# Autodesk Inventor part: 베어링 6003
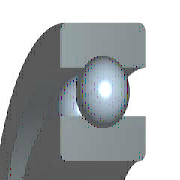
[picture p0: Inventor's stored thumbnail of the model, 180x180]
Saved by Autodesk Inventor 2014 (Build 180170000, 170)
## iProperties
Created: 2012-02
Part Number: 베어링 6003
Material: 강철, 연강
Description: 깊은 그루브 볼 베어링
Document SubType Name: Modeling
Standard: KS B 2023
Designer: mduedu
Standards Organization: KS
Language: ko-KR
Size Designation: 6003 - 17 x 35 x 10
Categories: <MemberInstance><Categories><Category DisplayName="샤프트 부품" InternalName="7f7aeb1f-a693-4053-b835-cee3144e0d98" Mnemonic="SHFT"><Category DisplayName="베어링" Inter
Density: 7.86 g/cm^3
Appearance: 주황색
Mass: 35.231 g
Surface Area: 48.7538 cm^2
Volume: 4.48231 cm^3
IsCustomPart: 1
Author: mduedu
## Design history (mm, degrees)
sketch "스케치" dims "d0" = 4.68 (= -0.26 x WD + 0.26 x BD)
  geometry: L1 (2.66, 13)-(7.34, 13); L2 (5, 13)-(5, 10.66); L3 (5, 13)-(5, 15.34); L4 (3.261, 11.434)-(0, 11.434); L5 (0, 8.5)-(10, 8.5); L6 (3.261, 14.566)-(0, 14.566); L7 (0, 17.5)-(10, 17.5); L8 (10, 8.5)-(10, 11.434); L9 (6.739, 11.434)-(10, 11.434); L10 (6.739, 14.566)-(10, 14.566); L11 (10, 17.5)-(10, 14.566); L12 (-1.4, 0)-(8.4, 0) reference; L13 (0, -0.3)-(0, 5.3) reference
  constraints: 22 end point, 4 point on line, 2 collinear, 2 perpendicular, 2 symmetric about line, 1 midpoint, 1 parallel, 14 other
  dimensions: "d9" = 17 diameter of L5 L12 (= WD); "d11" = 35 diameter of L7 L12 (= BD); "d12" = 10 distance between parallel lines of L8 L13 (= KB); "d13" = 22.868 diameter of L9 L12 (= 0.326 x BD + 0.674 x WD)
revolve "본체" stored, may be unused: angle "d6" = 90 deg
revolve "볼" stored, may be unused: angle "d7" = 90 deg
pattern_circular "IDS_ARRAYBALL[SIMPL:T]" dims angle "d3" = 360 deg
body "Solid1"
fillet "모깎기1" dims "d1" = 0.3 (= KRS)
other parameters: "WD" = 17 [user parameter; used in 5 equation terms], "BD" = 35 [user parameter; used in 5 equation terms], "KB" = 10 [user parameter; used in 1 equation term], "KRS" = 0.3 [user parameter; used in 1 equation term], "d4" = 0, "d5" = 0, "d8" = 0, "d14" = 0, "d15" = 0, "BBA" = 0 [user parameter], "BC0" = 3250000 [user parameter], "BC" = 6050000 [user parameter], "BR" = 17.5 (= 0.5 x BD) [user parameter], "WR" = 8.5 (= 0.5 x WD) [user parameter]
